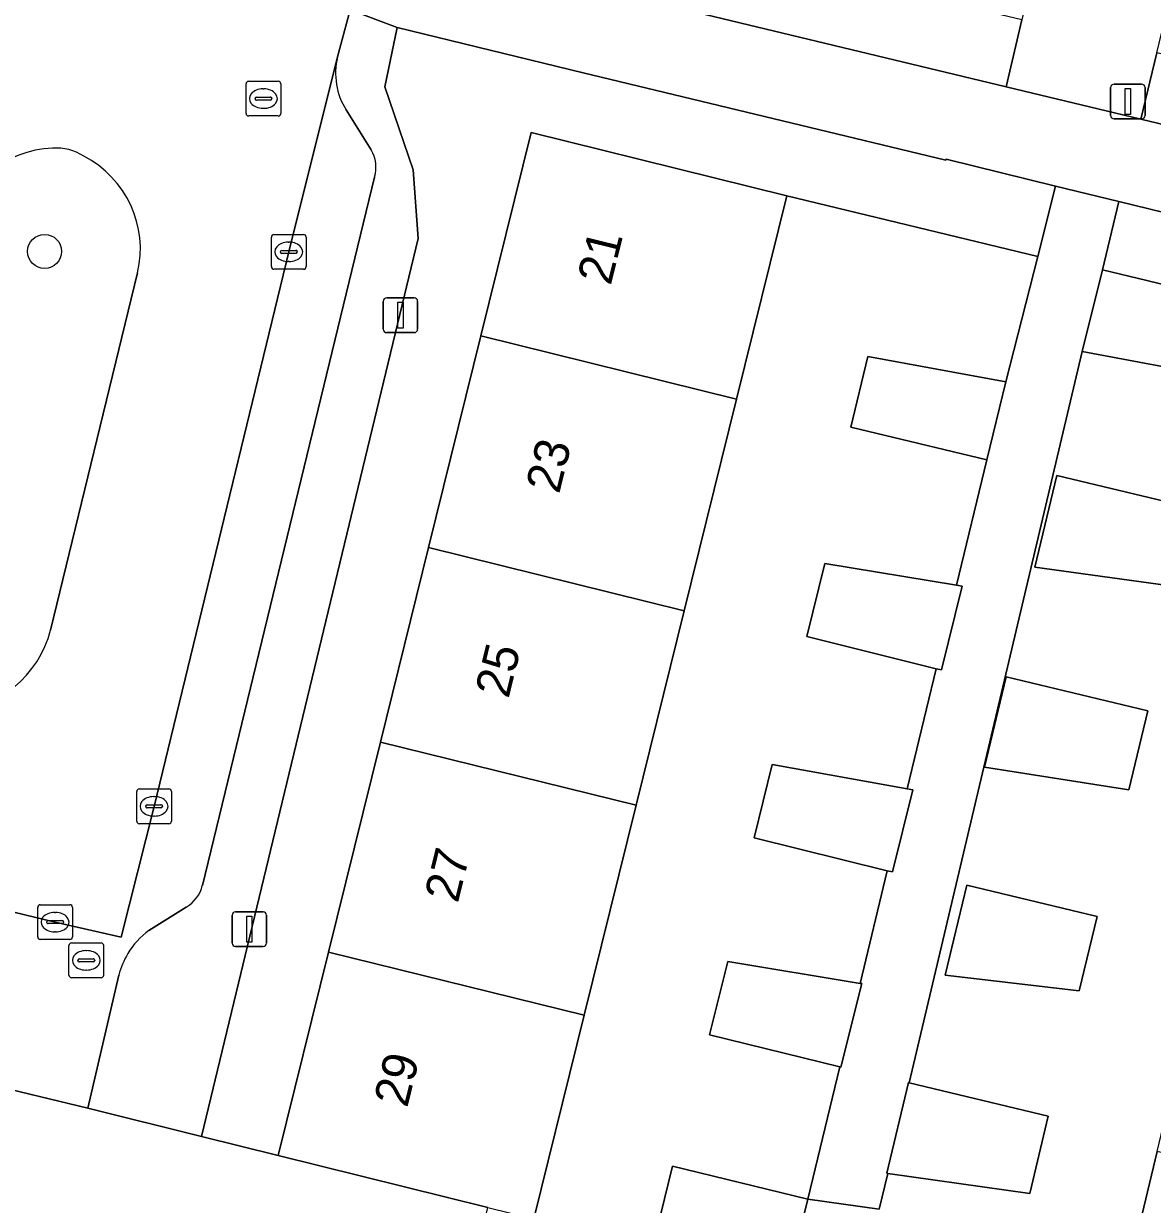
# Model space of a CAD drawing. Extents: x 162803 to 163818, y 381639 to 382475.
# Drawn here: x 163136.69 to 163169.18, y 382209.38 to 382243.37 of the extents above; entities that cross this region are included whole.
import ezdxf

# ---------------------------------------------------------------- set-up
doc = ezdxf.new("R2010")
doc.units = 0
for name, color, linetype in [('IMGEO_Boom', 7, 'Continuous'), ('IMGEO_Erf', 7, 'Continuous'), ('IMGEO_Groenvoorziening', 7, 'Continuous'), ('IMGEO_Hek', 7, 'Continuous'), ('IMGEO_Kolk', 7, 'Continuous'), ('IMGEO_Lichtmast', 7, 'Continuous'), ('IMGEO_Pand', 7, 'Continuous'), ('IMGEO_Pand_nummerreeks', 7, 'Continuous'), ('IMGEO_Parkeervlak_open', 7, 'Continuous'), ('IMGEO_Rijbaan_lokaal_open', 7, 'Continuous'), ('IMGEO_Rioolput', 7, 'Continuous'), ('IMGEO_Voetpad_open', 7, 'Continuous')]:
    doc.layers.add(name, color=color, linetype=linetype)

msp = doc.modelspace()

# ---------------------------------------------------------------- linework, layer by layer
at = {"layer": 'IMGEO_Boom'}
msp.add_circle((163137.294, 382236.817), 0.489, dxfattribs=at)
at = {"layer": 'IMGEO_Erf'}
for points in [[(163146.959, 382222.691), (163148.344, 382228.289), (163149.852, 382234.381), (163151.301, 382240.238), (163158.66, 382238.417), (163165.876, 382236.67), (163166.392, 382238.693), (163163.242, 382239.472), (163163.236, 382239.446), (163152.798, 382241.958), (163147.445, 382243.263), (163147.088, 382241.552), (163147.902, 382239.162), (163148.048, 382237.184), (163141.809, 382211.34), (163144.013, 382210.786), (163145.463, 382216.647)], [(163172.103, 382222.512), (163173.544, 382228.515), (163171.272, 382229.061), (163172.066, 382232.367), (163174.338, 382231.822), (163174.984, 382234.51), (163171.664, 382235.339), (163171.158, 382233.187), (163167.151, 382233.933), (163162.177, 382212.885), (163166.181, 382211.923), (163165.646, 382209.693), (163161.56, 382210.274), (163161.317, 382209.247), (163159.257, 382209.535), (163158.683, 382207.182), (163167.883, 382204.938), (163169.316, 382210.907), (163170.745, 382216.858)], [(163165.794, 382227.729), (163166.428, 382230.367), (163170.435, 382229.405), (163169.895, 382227.157)], [(163150.047, 382209.293), (163144.013, 382210.786), (163141.809, 382211.34), (163138.535, 382212.15), (163124.973, 382215.424), (163121.429, 382216.275), (163118.671, 382216.877), (163111.314, 382218.702), (163093.672, 382223), (163086.358, 382224.789), (163082.453, 382225.745), (163069.123, 382170.722), (163071.74, 382166.782), (163081.213, 382162.978), (163089.555, 382160.344), (163135.606, 382149.117)], [(163164.343, 382221.965), (163164.97, 382224.573), (163169.05, 382223.593), (163168.502, 382221.312)], [(163167.589, 382217.67), (163167.074, 382215.526), (163163.21, 382215.977), (163163.833, 382218.572)]]:
    msp.add_lwpolyline(points, close=True, dxfattribs=at)
msp.add_lwpolyline([(163154.787, 382208.132), (163155.361, 382210.485), (163159.257, 382209.535), (163160.179, 382213.339), (163156.433, 382214.266), (163156.956, 382216.378), (163160.762, 382215.745), (163161.547, 382218.988), (163157.716, 382219.936), (163158.237, 382222.041), (163162.118, 382221.344), (163162.956, 382224.804), (163159.231, 382225.726), (163159.751, 382227.828), (163163.538, 382227.205), (163164.412, 382230.813), (163160.5, 382231.757), (163160.989, 382233.787), (163164.954, 382233.058), (163165.876, 382236.67), (163158.66, 382238.417), (163157.211, 382232.56), (163155.704, 382226.468), (163154.319, 382220.87), (163152.823, 382214.827), (163151.373, 382208.965)], dxfattribs=at)
at = {"layer": 'IMGEO_Groenvoorziening'}
for points in [[(163154.299, 382246.14), (163146.893, 382247.921), (163143.732, 382248.734), (163143.272, 382246.834), (163146.526, 382246.03), (163152.35, 382244.592), (163164.968, 382241.557), (163165.416, 382243.483), (163161.513, 382244.425)], [(163174.805, 382241.277), (163169.303, 382242.529), (163168.844, 382240.625), (163189.262, 382235.713), (163190.286, 382235.467), (163190.746, 382237.354), (163184.898, 382238.854)], [(163169.509, 382237.937), (163168.215, 382238.248), (163167.743, 382236.285), (163169.019, 382235.977), (163171.664, 382235.339), (163174.984, 382234.51), (163182.321, 382232.741), (163188.207, 382231.249), (163188.703, 382233.318)]]:
    msp.add_lwpolyline(points, close=True, dxfattribs=at)
msp.add_lwpolyline([(163137.465, 382225.917), (163139.971, 382236.202)], dxfattribs=at)
for centre, radius, start, end in [((163137.644, 382236.677), 3.112, 92.1882, 165.0199), ((163137.638, 382238.373), 1.418, 56.6478, 94.5863), ((163137.047, 382236.886), 3.003, 346.8415, 62.8365), ((163134.437, 382226.69), 3.125, 273.367, 345.671)]:
    msp.add_arc(centre, radius, start, end, dxfattribs=at)
at = {"layer": 'IMGEO_Hek'}
msp.add_lwpolyline([(163144.013, 382210.786), (163141.809, 382211.34)], dxfattribs=at)
at = {"layer": 'IMGEO_Kolk'}
for p, q in [((163143.82, 382236.377), (163143.82, 382237.229)), ((163143.895, 382237.303), (163144.747, 382237.303)), ((163144.821, 382237.229), (163144.821, 382236.377)), ((163144.079, 382236.797), (163144.079, 382236.809)), ((163144.122, 382236.846), (163144.52, 382236.846)), ((163144.308, 382237.083), (163144.333, 382237.083)), ((163144.563, 382236.809), (163144.563, 382236.797)), ((163144.517, 382236.76), (163144.119, 382236.76)), ((163144.331, 382236.523), (163144.306, 382236.523)), ((163144.747, 382236.303), (163143.895, 382236.303)), ((163139.943, 382220.415), (163139.943, 382221.267)), ((163140.018, 382221.341), (163140.87, 382221.341)), ((163140.944, 382221.267), (163140.944, 382220.415)), ((163140.202, 382220.835), (163140.202, 382220.847)), ((163140.64, 382220.798), (163140.242, 382220.798)), ((163140.245, 382220.884), (163140.643, 382220.884)), ((163140.431, 382221.121), (163140.456, 382221.121)), ((163140.686, 382220.847), (163140.686, 382220.835)), ((163140.454, 382220.561), (163140.429, 382220.561)), ((163140.87, 382220.341), (163140.018, 382220.341)), ((163137.094, 382217.081), (163137.094, 382217.933)), ((163137.169, 382218.007), (163138.021, 382218.007)), ((163137.582, 382217.787), (163137.607, 382217.787)), ((163138.095, 382217.933), (163138.095, 382217.081)), ((163137.353, 382217.501), (163137.353, 382217.513)), ((163137.791, 382217.464), (163137.393, 382217.464)), ((163137.396, 382217.55), (163137.794, 382217.55)), ((163137.837, 382217.513), (163137.837, 382217.501)), ((163137.605, 382217.227), (163137.58, 382217.227)), ((163138.021, 382217.007), (163137.169, 382217.007))]:
    msp.add_line(p, q, dxfattribs=at)
for points in [[(163143.82, 382236.377), (163143.82, 382237.229)], [(163143.895, 382237.303), (163144.747, 382237.303)], [(163144.821, 382237.229), (163144.821, 382236.377)], [(163144.747, 382236.303), (163143.895, 382236.303)], [(163139.943, 382220.415), (163139.943, 382221.267)], [(163140.018, 382221.341), (163140.87, 382221.341)], [(163140.944, 382221.267), (163140.944, 382220.415)], [(163140.87, 382220.341), (163140.018, 382220.341)], [(163137.094, 382217.081), (163137.094, 382217.933)], [(163137.169, 382218.007), (163138.021, 382218.007)], [(163138.095, 382217.933), (163138.095, 382217.081)], [(163138.021, 382217.007), (163137.169, 382217.007)]]:
    msp.add_lwpolyline(points, dxfattribs=at)
for centre, radius, start, end in [((163143.897, 382237.227), 0.0765, 91.552, 178.448), ((163143.897, 382237.227), 0.0765, 91.552, 178.448), ((163144.745, 382237.227), 0.0765, 1.552, 88.448), ((163144.745, 382237.227), 0.0765, 1.552, 88.448), ((163144.119, 382236.806), 0.0403, 85.8775, 175.7526), ((163144.116, 382236.796), 0.0366, 178.938, 274.7102), ((163144.52, 382236.803), 0.043, 264.8664, 352.4533), ((163144.524, 382236.808), 0.0386, 1.7309, 96.639), ((163143.897, 382236.379), 0.0765, 181.552, 268.448), ((163143.897, 382236.379), 0.0765, 181.552, 268.448), ((163144.745, 382236.379), 0.0765, 271.552, 358.448), ((163144.745, 382236.379), 0.0765, 271.552, 358.448), ((163140.02, 382221.265), 0.0765, 91.552, 178.448), ((163140.02, 382221.265), 0.0765, 91.552, 178.448), ((163140.868, 382221.265), 0.0765, 1.552, 88.448), ((163140.868, 382221.265), 0.0765, 1.552, 88.448), ((163140.242, 382220.844), 0.0403, 85.8775, 175.7526), ((163140.239, 382220.834), 0.0366, 178.938, 274.7102), ((163140.643, 382220.841), 0.043, 264.8664, 352.4533), ((163140.647, 382220.846), 0.0386, 1.7309, 96.639), ((163140.02, 382220.417), 0.0765, 181.552, 268.448), ((163140.02, 382220.417), 0.0765, 181.552, 268.448), ((163140.868, 382220.417), 0.0765, 271.552, 358.448), ((163140.868, 382220.417), 0.0765, 271.552, 358.448), ((163137.171, 382217.931), 0.0765, 91.552, 178.448), ((163137.171, 382217.931), 0.0765, 91.552, 178.448), ((163138.019, 382217.931), 0.0765, 1.552, 88.448), ((163138.019, 382217.931), 0.0765, 1.552, 88.448), ((163137.393, 382217.51), 0.0403, 85.8775, 175.7526), ((163137.39, 382217.5), 0.0366, 178.938, 274.7102), ((163137.794, 382217.507), 0.043, 264.8664, 352.4533), ((163137.798, 382217.512), 0.0386, 1.7309, 96.639), ((163137.171, 382217.083), 0.0765, 181.552, 268.448), ((163137.171, 382217.083), 0.0765, 181.552, 268.448), ((163138.019, 382217.083), 0.0765, 271.552, 358.448), ((163138.019, 382217.083), 0.0765, 271.552, 358.448)]:
    msp.add_arc(centre, radius, start, end, dxfattribs=at)
for centre, major_axis, ratio, start_param, end_param in [((163144.307, 382236.803), (-0.387, 0.002), 0.722429, 4.712389, 7.853982), ((163144.332, 382236.803), (-0.39, 0.002), 0.717154, 1.570796, 4.712389), ((163140.43, 382220.841), (-0.387, 0.002), 0.722429, 4.712389, 7.853982), ((163140.455, 382220.841), (-0.39, 0.002), 0.717154, 1.570796, 4.712389), ((163137.581, 382217.507), (-0.387, 0.002), 0.722429, 4.712389, 7.853982), ((163137.606, 382217.507), (-0.39, 0.002), 0.717154, 1.570796, 4.712389)]:
    msp.add_ellipse(centre, major_axis=major_axis, ratio=ratio, start_param=start_param, end_param=end_param, dxfattribs=at)
at = {"layer": 'IMGEO_Lichtmast'}
for p, q in [((163167.975, 382240.732), (163167.975, 382241.532)), ((163167.975, 382241.532), (163167.975, 382240.732)), ((163168.075, 382241.632), (163168.865, 382241.632)), ((163168.865, 382241.632), (163168.075, 382241.632)), ((163168.965, 382241.532), (163168.965, 382240.732)), ((163168.965, 382240.732), (163168.965, 382241.532)), ((163168.865, 382240.632), (163168.075, 382240.632)), ((163168.075, 382240.632), (163168.865, 382240.632)), ((163147.139, 382235.478), (163147.929, 382235.478)), ((163147.929, 382235.478), (163147.139, 382235.478)), ((163147.039, 382234.578), (163147.039, 382235.378)), ((163147.039, 382235.378), (163147.039, 382234.578)), ((163148.029, 382235.378), (163148.029, 382234.578)), ((163148.029, 382234.578), (163148.029, 382235.378)), ((163147.929, 382234.478), (163147.139, 382234.478)), ((163147.139, 382234.478), (163147.929, 382234.478)), ((163142.791, 382217.805), (163143.581, 382217.805)), ((163143.581, 382217.805), (163142.791, 382217.805)), ((163142.691, 382216.905), (163142.691, 382217.705)), ((163142.691, 382217.705), (163142.691, 382216.905)), ((163143.681, 382217.705), (163143.681, 382216.905)), ((163143.681, 382216.905), (163143.681, 382217.705)), ((163143.581, 382216.805), (163142.791, 382216.805)), ((163142.791, 382216.805), (163143.581, 382216.805))]:
    msp.add_line(p, q, dxfattribs=at)
for points in [[(163168.395, 382241.507), (163168.545, 382241.507), (163168.545, 382240.757), (163168.395, 382240.757), (163168.395, 382241.507)], [(163147.459, 382235.353), (163147.609, 382235.353), (163147.609, 382234.603), (163147.459, 382234.603), (163147.459, 382235.353)], [(163143.111, 382217.68), (163143.261, 382217.68), (163143.261, 382216.93), (163143.111, 382216.93), (163143.111, 382217.68)]]:
    msp.add_lwpolyline(points, dxfattribs=at)
for centre, start, end in [((163168.075, 382241.532), 90, 180), ((163168.075, 382241.532), 90, 180), ((163168.865, 382241.532), 0, 90), ((163168.865, 382241.532), 360, 90), ((163168.075, 382240.732), 180, 270), ((163168.075, 382240.732), 180, 270), ((163168.865, 382240.732), 270, 0), ((163168.865, 382240.732), 270, 0), ((163147.139, 382235.378), 90, 180), ((163147.139, 382235.378), 90, 180), ((163147.929, 382235.378), 0, 90), ((163147.929, 382235.378), 360, 90), ((163147.139, 382234.578), 180, 270), ((163147.139, 382234.578), 180, 270), ((163147.929, 382234.578), 270, 0), ((163147.929, 382234.578), 270, 0), ((163142.791, 382217.705), 90, 180), ((163142.791, 382217.705), 90, 180), ((163143.581, 382217.705), 0, 90), ((163143.581, 382217.705), 360, 90), ((163142.791, 382216.905), 180, 270), ((163142.791, 382216.905), 180, 270), ((163143.581, 382216.905), 270, 0), ((163143.581, 382216.905), 270, 0)]:
    msp.add_arc(centre, 0.1, start, end, dxfattribs=at)
at = {"layer": 'IMGEO_Pand'}
for points in [[(163157.211, 382232.56), (163158.66, 382238.417), (163151.301, 382240.238), (163149.852, 382234.381)], [(163169.019, 382235.977), (163167.743, 382236.285), (163167.151, 382233.933), (163171.158, 382233.187), (163171.664, 382235.339)], [(163157.211, 382232.56), (163149.852, 382234.381), (163148.344, 382228.289), (163155.704, 382226.468)], [(163164.412, 382230.813), (163164.954, 382233.058), (163160.989, 382233.787), (163160.5, 382231.757)], [(163169.895, 382227.157), (163170.435, 382229.405), (163166.428, 382230.367), (163165.794, 382227.729)], [(163154.319, 382220.87), (163155.704, 382226.468), (163148.344, 382228.289), (163146.959, 382222.691)], [(163163.538, 382227.205), (163159.751, 382227.828), (163159.231, 382225.726), (163162.956, 382224.804), (163163.103, 382224.768), (163163.699, 382227.179)], [(163168.502, 382221.312), (163169.05, 382223.593), (163164.97, 382224.573), (163164.343, 382221.965)], [(163154.319, 382220.87), (163146.959, 382222.691), (163145.463, 382216.647), (163152.823, 382214.827)], [(163162.118, 382221.344), (163158.237, 382222.041), (163157.716, 382219.936), (163161.547, 382218.988), (163161.696, 382218.951), (163162.281, 382221.315)], [(163167.074, 382215.526), (163167.589, 382217.67), (163163.833, 382218.572), (163163.21, 382215.977)], [(163152.823, 382214.827), (163145.463, 382216.647), (163144.013, 382210.786), (163150.047, 382209.293), (163151.373, 382208.965)], [(163160.762, 382215.745), (163156.956, 382216.378), (163156.433, 382214.266), (163160.179, 382213.339), (163160.214, 382213.33), (163160.81, 382215.737)], [(163162.177, 382212.885), (163162.158, 382212.889), (163161.531, 382210.278), (163161.56, 382210.274), (163165.646, 382209.693), (163166.181, 382211.923)], [(163169.316, 382210.907), (163167.883, 382204.938), (163175.19, 382203.175), (163176.63, 382209.144)], [(163154.787, 382208.132), (163158.683, 382207.182), (163159.257, 382209.535), (163155.361, 382210.485)]]:
    msp.add_lwpolyline(points, close=True, dxfattribs=at)
at = {"layer": 'IMGEO_Parkeervlak_open'}
for points in [[(163145.726, 382242.413), (163144.32, 382236.804), (163140.443, 382220.841), (163139.498, 382217.076), (163137.595, 382217.507), (163127.997, 382219.832), (163126.177, 382220.3), (163125.897, 382219.282), (163124.973, 382215.424), (163138.535, 382212.15), (163139.43, 382215.984)], [(163146.69, 382239.737), (163145.972, 382240.887)], [(163141.833, 382218.56), (163146.791, 382238.957)], [(163140.293, 382217.27), (163141.371, 382217.94)]]:
    msp.add_lwpolyline(points, dxfattribs=at)
for centre, radius, start, end in [((163147.649, 382241.94), 1.981, 166.1911, 212.1242), ((163145.86, 382239.233), 0.971, 343.4783, 31.2777), ((163140.871, 382218.795), 0.99, 300.3235, 346.2924), ((163141.707, 382215.386), 2.355, 126.891, 148.955), ((163141.661, 382215.41), 2.304, 148.8786, 165.5787)]:
    msp.add_arc(centre, radius, start, end, dxfattribs=at)
at = {"layer": 'IMGEO_Rijbaan_lokaal_open'}
for points in [[(163136.382, 382246.138), (163136.184, 382246.175), (163132.637, 382247.045), (163132.31, 382245.931), (163132.188, 382245.406), (163131.05, 382240.49), (163127.154, 382224.374), (163126.177, 382220.3), (163127.997, 382219.832), (163137.595, 382217.507), (163139.498, 382217.076), (163140.443, 382220.841), (163144.32, 382236.804), (163145.726, 382242.413)], [(163145.726, 382242.413), (163146.086, 382243.768), (163144.497, 382244.161), (163143.74, 382244.321), (163143.654, 382244.338), (163143.569, 382244.359), (163136.694, 382246.075)], [(163139.971, 382236.202), (163137.465, 382225.917)]]:
    msp.add_lwpolyline(points, dxfattribs=at)
for centre, radius, start, end in [((163137.644, 382236.677), 3.112, 92.1882, 165.0199), ((163137.638, 382238.373), 1.418, 56.6478, 94.5863), ((163137.047, 382236.886), 3.003, 346.8415, 62.8365), ((163134.437, 382226.69), 3.125, 273.367, 345.671)]:
    msp.add_arc(centre, radius, start, end, dxfattribs=at)
at = {"layer": 'IMGEO_Rioolput'}
for p, q in [((163143.09, 382240.788), (163143.09, 382241.64)), ((163143.165, 382241.714), (163144.017, 382241.714)), ((163144.091, 382241.64), (163144.091, 382240.788)), ((163143.349, 382241.208), (163143.349, 382241.22)), ((163143.392, 382241.257), (163143.79, 382241.257)), ((163143.578, 382241.494), (163143.603, 382241.494)), ((163143.833, 382241.22), (163143.833, 382241.208)), ((163143.787, 382241.171), (163143.389, 382241.171)), ((163143.601, 382240.934), (163143.576, 382240.934)), ((163144.017, 382240.714), (163143.165, 382240.714)), ((163137.992, 382215.982), (163137.992, 382216.834)), ((163138.067, 382216.908), (163138.919, 382216.908)), ((163138.993, 382216.834), (163138.993, 382215.982)), ((163138.251, 382216.402), (163138.251, 382216.414)), ((163138.294, 382216.451), (163138.692, 382216.451)), ((163138.48, 382216.688), (163138.505, 382216.688)), ((163138.735, 382216.414), (163138.735, 382216.402)), ((163138.689, 382216.365), (163138.291, 382216.365)), ((163138.503, 382216.128), (163138.478, 382216.128)), ((163138.919, 382215.908), (163138.067, 382215.908))]:
    msp.add_line(p, q, dxfattribs=at)
for points in [[(163143.09, 382240.788), (163143.09, 382241.64)], [(163143.165, 382241.714), (163144.017, 382241.714)], [(163144.091, 382241.64), (163144.091, 382240.788)], [(163144.017, 382240.714), (163143.165, 382240.714)], [(163137.992, 382215.982), (163137.992, 382216.834)], [(163138.067, 382216.908), (163138.919, 382216.908)], [(163138.993, 382216.834), (163138.993, 382215.982)], [(163138.919, 382215.908), (163138.067, 382215.908)]]:
    msp.add_lwpolyline(points, dxfattribs=at)
for centre, radius, start, end in [((163143.167, 382241.638), 0.0765, 91.552, 178.448), ((163143.167, 382241.638), 0.0765, 91.552, 178.448), ((163144.015, 382241.638), 0.0765, 1.552, 88.448), ((163144.015, 382241.638), 0.0765, 1.552, 88.448), ((163143.389, 382241.217), 0.0403, 85.8775, 175.7526), ((163143.386, 382241.207), 0.0366, 178.938, 274.7102), ((163143.79, 382241.214), 0.043, 264.8664, 352.4533), ((163143.794, 382241.219), 0.0386, 1.7309, 96.639), ((163143.167, 382240.79), 0.0765, 181.552, 268.448), ((163143.167, 382240.79), 0.0765, 181.552, 268.448), ((163144.015, 382240.79), 0.0765, 271.552, 358.448), ((163144.015, 382240.79), 0.0765, 271.552, 358.448), ((163138.069, 382216.832), 0.0765, 91.552, 178.448), ((163138.069, 382216.832), 0.0765, 91.552, 178.448), ((163138.917, 382216.832), 0.0765, 1.552, 88.448), ((163138.917, 382216.832), 0.0765, 1.552, 88.448), ((163138.291, 382216.411), 0.0403, 85.8775, 175.7526), ((163138.288, 382216.401), 0.0366, 178.938, 274.7102), ((163138.692, 382216.408), 0.043, 264.8664, 352.4533), ((163138.696, 382216.413), 0.0386, 1.7309, 96.639), ((163138.069, 382215.984), 0.0765, 181.552, 268.448), ((163138.069, 382215.984), 0.0765, 181.552, 268.448), ((163138.917, 382215.984), 0.0765, 271.552, 358.448), ((163138.917, 382215.984), 0.0765, 271.552, 358.448)]:
    msp.add_arc(centre, radius, start, end, dxfattribs=at)
for centre, major_axis, ratio, start_param, end_param in [((163143.577, 382241.214), (-0.387, 0.002), 0.722429, 4.712389, 7.853982), ((163143.602, 382241.214), (-0.39, 0.002), 0.717154, 1.570796, 4.712389), ((163138.479, 382216.408), (-0.387, 0.002), 0.722429, 4.712389, 7.853982), ((163138.504, 382216.408), (-0.39, 0.002), 0.717154, 1.570796, 4.712389)]:
    msp.add_ellipse(centre, major_axis=major_axis, ratio=ratio, start_param=start_param, end_param=end_param, dxfattribs=at)
at = {"layer": 'IMGEO_Voetpad_open'}
for points in [[(163174.478, 382263.53), (163175.063, 382265.964), (163175.938, 382269.391), (163172.175, 382270.465), (163170.455, 382263.623), (163170.515, 382263.613), (163169.935, 382261.207), (163169.853, 382261.227), (163165.967, 382245.764), (163165.416, 382243.483), (163164.968, 382241.557), (163168.844, 382240.625), (163169.303, 382242.529), (163170.232, 382246.387), (163170.788, 382248.691), (163171.602, 382251.937), (163172.221, 382254.514)], [(163167.151, 382233.933), (163167.743, 382236.285), (163168.215, 382238.248), (163166.392, 382238.693), (163165.876, 382236.67), (163164.954, 382233.058), (163164.412, 382230.813), (163163.538, 382227.205), (163163.699, 382227.179), (163163.103, 382224.768), (163162.956, 382224.804), (163162.118, 382221.344), (163162.281, 382221.315), (163161.696, 382218.951), (163161.547, 382218.988), (163160.762, 382215.745), (163160.81, 382215.737), (163160.214, 382213.33), (163160.179, 382213.339), (163159.257, 382209.535), (163161.317, 382209.247), (163161.56, 382210.274), (163161.531, 382210.278), (163162.158, 382212.889), (163162.177, 382212.885)]]:
    msp.add_lwpolyline(points, close=True, dxfattribs=at)
for points in [[(163168.844, 382240.625), (163164.968, 382241.557), (163152.35, 382244.592), (163146.526, 382246.03), (163143.272, 382246.834), (163142.397, 382247.069)], [(163143.569, 382244.359), (163143.654, 382244.338), (163143.74, 382244.321), (163144.497, 382244.161), (163146.086, 382243.768), (163147.445, 382243.263), (163152.798, 382241.958), (163163.236, 382239.446), (163163.242, 382239.472), (163166.392, 382238.693), (163168.215, 382238.248), (163169.509, 382237.937), (163188.703, 382233.318), (163189.262, 382235.713), (163168.844, 382240.625)], [(163148.048, 382237.184), (163147.902, 382239.162), (163147.088, 382241.552), (163147.445, 382243.263), (163146.086, 382243.768), (163145.726, 382242.413)], [(163145.972, 382240.887), (163146.69, 382239.737)], [(163146.791, 382238.957), (163141.833, 382218.56)], [(163139.43, 382215.984), (163138.535, 382212.15), (163141.809, 382211.34), (163148.048, 382237.184)], [(163141.371, 382217.94), (163140.293, 382217.27)]]:
    msp.add_lwpolyline(points, dxfattribs=at)
for centre, radius, start, end in [((163147.649, 382241.94), 1.981, 166.1911, 212.1242), ((163145.86, 382239.233), 0.971, 343.4783, 31.2777), ((163140.871, 382218.795), 0.99, 300.3235, 346.2924), ((163141.707, 382215.386), 2.355, 126.891, 148.955), ((163141.661, 382215.41), 2.304, 148.8786, 165.5787)]:
    msp.add_arc(centre, radius, start, end, dxfattribs=at)

# ---------------------------------------------------------------- texts
at = {"layer": 'IMGEO_Pand_nummerreeks'}
for s, p in [('21', (163153.584, 382235.813)), ('23', (163152.1, 382229.813)), ('25', (163150.642, 382223.922)), ('27', (163149.184, 382218.032)), ('29', (163147.727, 382212.142))]:
    msp.add_text(s, height=1, rotation=76.1012, dxfattribs=at).set_placement(p)

doc.saveas('drawing.dxf')
